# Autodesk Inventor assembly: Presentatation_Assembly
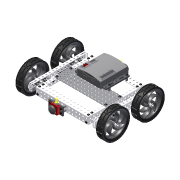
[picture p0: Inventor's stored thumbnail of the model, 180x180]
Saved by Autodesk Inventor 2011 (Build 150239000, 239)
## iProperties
Created: 2007-12
Part Number: Presentatation_Assembly
Document SubType Name: Assembly
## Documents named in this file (15)
- C:\Data Folder\VEX 2011\Inventor Datasets\Unit 16\Wiring_Assembly.iam
- C:\Data Folder\VEX 2011\Inventor Datasets\Unit 16\Components\SCREW-832-0250.ipt
- C:\Data Folder\VEX 2011\Inventor Datasets\Unit 16\Components\NUT-832-KEPS.iam
- C:\Data Folder\VEX 2011\Inventor Datasets\Unit 16\Components\VL-RAIL-21-16 RevA.ipt
- C:\Data Folder\VEX 2011\Inventor Datasets\Unit 16\Components\ANG-HH22-15-SK RevA.ipt
- C:\Data Folder\VEX 2011\Inventor Datasets\Unit 16\Components\VL-PLATE-5-15 RevA.ipt
- C:\Data Folder\VEX 2011\Inventor Datasets\Unit 16\Components\Wheel _Assembly.iam
- C:\Data Folder\VEX 2011\Inventor Datasets\Unit 16\Components\BEAM-0500.ipt
- C:\Data Folder\VEX 2011\Inventor Datasets\Unit 16\Components\MicroController View.iam
- C:\Data Folder\VEX 2011\Inventor Datasets\Unit 16\Components\BUMPER-SWITCH.iam
- C:\Data Folder\VEX 2011\Inventor Datasets\Unit 16\Components\BUMPER-SWITCH_MIR.iam
- C:\Data Folder\VEX 2011\Inventor Datasets\Unit 16\Components\BEAM-0500_MIR.ipt
- C:\Data Folder\VEX 2011\Inventor Datasets\Unit 16\Connector_01.ipt
- C:\Data Folder\VEX 2011\Inventor Datasets\Unit 16\Content Center\en-US\ANSI B18.3(03)\ANSI B18.3 - 8-32 UNC - UNC - 0.5(1).ipt
- C:\Data Folder\VEX 2011\Inventor Datasets\Unit 16\Content Center\en-US\ANSI B18.3(03)\ANSI B18.3 - 8-32 UNC - UNC - 0.375(1).ipt
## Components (70 placed, 14 different names)
1. BEAM-0500:1 — Mate:151, Mate:152
2. SCREW-832-0250:1 — Mate:57, Flush:10
3. SCREW-832-0250:6
4. SCREW-832-0250:14 — Mate:56, Flush:10
5. SCREW-832-0250:18
6. SCREW-832-0250:20
7. SCREW-832-0250:21
8. NUT-832-KEPS:14 [sub-assembly]
9. NUT-832-KEPS:16 [sub-assembly] — Mate:54, Mate:55, Mate:56
10. NUT-832-KEPS:17 [sub-assembly]
11. NUT-832-KEPS:18 [sub-assembly] — Mate:57, Mate:58
12. NUT-832-KEPS:19 [sub-assembly]
13. NUT-832-KEPS:20 [sub-assembly]
14. NUT-832-KEPS:21 [sub-assembly]
15. NUT-832-KEPS:22 [sub-assembly]
16. NUT-832-KEPS:23 [sub-assembly]
17. SCREW-832-0250:25
18. SCREW-832-0250:34
19. SCREW-832-0250:30 — Mate:59, Mate:60, Mate:61
20. ANG-HH22-15-SK RevA:1 — Mate:2, Mate:3, Mate:4, Flush:2, Mate:6, Mate:154, Mate:156
21. NUT-832-KEPS:24 [sub-assembly] — Mate:183, Mate:184
22. SCREW-832-0250:40
23. SCREW-832-0250:42
24. SCREW-832-0250:43 — Mate:169, Mate:170
25. SCREW-832-0250:44 — Mate:163, Mate:164
26. SCREW-832-0250:45 — Mate:165, Mate:166
27. SCREW-832-0250:46 — Mate:167, Mate:168
28. SCREW-832-0250:47 — Mate:171, Mate:172, Mate:173
29. SCREW-832-0250:48 — Mate:179, Mate:180, Mate:183
30. SCREW-832-0250:49 — Mate:175, Mate:176, Mate:181
31. SCREW-832-0250:50 — Mate:177, Mate:178, Mate:185
32. NUT-832-KEPS:31 [sub-assembly] — Mate:181, Mate:182
33. NUT-832-KEPS:32 [sub-assembly] — Mate:185, Mate:186
34. VL-RAIL-21-16 RevA:3 — Mate:2, Mate:3, Mate:4, Flush:3, Mate:8, Mate:9, Mate:54, Mate:55, Mate:58, Mate:59, Mate:60, Mate:62, Flush:12, Mate:148, Mate:149, Mate:150, Mate:177, Mate:179, Mate:184, Mate:186
35. NUT-832-KEPS:28 [sub-assembly] — Mate:61, Mate:62
36. VL-RAIL-21-16 RevA:4 — Flush:2, Mate:6, Mate:102, Mate:159, Mate:160, Mate:161, Mate:162, Mate:171, Mate:174, Mate:175, Mate:182
37. ANG-HH22-15-SK RevA:2 — Flush:3, Mate:8, Mate:9, Mate:113, Angle:2, Mate:114, Mate:160, Mate:164, Mate:166, Mate:168, Mate:170
38. NUT-832-KEPS:27 [sub-assembly] — Mate:173, Mate:174
39. NUT-832-KEPS:30 [sub-assembly]
40. VL-PLATE-5-15 RevA:1 — Mate:102, Mate:158, Mate:172, Mate:176, Mate:178, Mate:180
41. Wheel _Assembly:1 [sub-assembly] — Flush:12, Mate:148, Mate:149, Mate:150
42. Wheel _Assembly:2 [sub-assembly] — Mate:159, Mate:161, Mate:162
43. MicroController View:1 [sub-assembly] — Mate:128, Mate:129, Mate:132, Mate:133, Mate:134, Mate:135, Mate:136, Mate:137, Mate:138, Mate:139, Mate:152, Mate:187, Mate:188
44. BUMPER-SWITCH:1 [sub-assembly] — Mate:115, Mate:116, Mate:117, Mate:140, Mate:142, Mate:144, Mate:146
45. BUMPER-SWITCH_MIR:1 [sub-assembly] — Mate:118, Mate:119, Mate:120, Insert:1, Insert:2, Insert:3, Insert:4
46. BEAM-0500_MIR:1
47. BEAM-0500_MIR:2 — Mate:118
48. BEAM-0500_MIR:3
49. BEAM-0500_MIR:4 — Mate:119, Mate:120
50. Hexagon Socket Button Head Cap Screw - Inch 8 - 32 x 1/2:3 — Mate:136, Mate:137, Mate:157
51. Hexagon Socket Button Head Cap Screw - Inch 8 - 32 x 1/2:1 — Mate:132, Mate:133, Mate:151
52. Hexagon Socket Button Head Cap Screw - Inch 8 - 32 x 1/2:2 — Mate:134, Mate:135, Mate:153
53. Hexagon Socket Button Head Cap Screw - Inch 8 - 32 x 1/2:4 — Mate:138, Mate:139, Mate:155
54. Hexagon Socket Button Head Cap Screw - Inch 8 - 32 x 3/8:1 — Mate:140, Mate:141
55. Hexagon Socket Button Head Cap Screw - Inch 8 - 32 x 3/8:2 — Mate:142, Mate:143
56. Hexagon Socket Button Head Cap Screw - Inch 8 - 32 x 3/8:3 — Mate:146, Mate:147
57. Hexagon Socket Button Head Cap Screw - Inch 8 - 32 x 3/8:4 — Mate:144, Mate:145
58. BEAM-0500:9 — Mate:153, Mate:154
59. BEAM-0500:10 — Mate:155, Mate:156
60. BEAM-0500:11 — Mate:157, Mate:158
61. Hexagon Socket Button Head Cap Screw - Inch 8 - 32 x 1/2:5 — Insert:4
62. Hexagon Socket Button Head Cap Screw - Inch 8 - 32 x 1/2:6 — Insert:3
63. Hexagon Socket Button Head Cap Screw - Inch 8 - 32 x 1/2:7 — Insert:2
64. Hexagon Socket Button Head Cap Screw - Inch 8 - 32 x 3/8:5 — Insert:1
65. Connector_01:1 — Mate:128, Mate:129, Flush:13
66. Connector_01:2 — Flush:13, Mate:187, Mate:188
67. BEAM-0500:5 — Mate:113, Angle:2, Mate:114, Mate:147, Mate:169
68. BEAM-0500:6 — Mate:116, Mate:143, Mate:165
69. BEAM-0500:7 — Mate:145, Mate:167
70. BEAM-0500:8 — Mate:115, Mate:117, Mate:141, Mate:163
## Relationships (93: Mate 83, Flush 5, Insert 4, Angle 1)
- Mate:2: ANG-HH22-15-SK RevA:1 ↔ VL-RAIL-21-16 RevA:3
- Mate:3: ANG-HH22-15-SK RevA:1 ↔ VL-RAIL-21-16 RevA:3
- Mate:4: ANG-HH22-15-SK RevA:1 ↔ VL-RAIL-21-16 RevA:3
- Flush:2: ANG-HH22-15-SK RevA:1 ↔ VL-RAIL-21-16 RevA:4
- Mate:6: ANG-HH22-15-SK RevA:1 ↔ VL-RAIL-21-16 RevA:4
- Flush:3: VL-RAIL-21-16 RevA:3 ↔ ANG-HH22-15-SK RevA:2
- Mate:8: VL-RAIL-21-16 RevA:3 ↔ ANG-HH22-15-SK RevA:2
- Mate:9: VL-RAIL-21-16 RevA:3 ↔ ANG-HH22-15-SK RevA:2
- Mate:54: NUT-832-KEPS:16 ↔ VL-RAIL-21-16 RevA:3
- Mate:55: NUT-832-KEPS:16 ↔ VL-RAIL-21-16 RevA:3
- Mate:56: SCREW-832-0250:14 ↔ NUT-832-KEPS:16
- Mate:57: SCREW-832-0250:1 ↔ NUT-832-KEPS:18
- Mate:58: NUT-832-KEPS:18 ↔ VL-RAIL-21-16 RevA:3
- Flush:10: SCREW-832-0250:1 ↔ SCREW-832-0250:14
- Mate:59: SCREW-832-0250:30 ↔ VL-RAIL-21-16 RevA:3
- Mate:60: SCREW-832-0250:30 ↔ VL-RAIL-21-16 RevA:3
- Mate:61: SCREW-832-0250:30 ↔ NUT-832-KEPS:28
- Mate:62: VL-RAIL-21-16 RevA:3 ↔ NUT-832-KEPS:28
- Mate:102: VL-RAIL-21-16 RevA:4 ↔ VL-PLATE-5-15 RevA:1
- Mate:113: ANG-HH22-15-SK RevA:2 ↔ BEAM-0500:5
- Angle:2: ANG-HH22-15-SK RevA:2 ↔ BEAM-0500:5
- Mate:114: ANG-HH22-15-SK RevA:2 ↔ BEAM-0500:5
- Mate:115: BUMPER-SWITCH:1 ↔ BEAM-0500:8
- Mate:116: BUMPER-SWITCH:1 ↔ BEAM-0500:6
- Mate:117: BUMPER-SWITCH:1 ↔ BEAM-0500:8
- Mate:118: BUMPER-SWITCH_MIR:1 ↔ BEAM-0500_MIR:2
- Mate:119: BUMPER-SWITCH_MIR:1 ↔ BEAM-0500_MIR:4
- Mate:120: BUMPER-SWITCH_MIR:1 ↔ BEAM-0500_MIR:4
- Mate:128: MicroController View:1 ↔ Connector_01:1
- Mate:129: MicroController View:1 ↔ Connector_01:1
- Mate:132: MicroController View:1 ↔ Hexagon Socket Button Head Cap Screw - Inch 8 - 32 x 1/2:1
- Mate:133: MicroController View:1 ↔ Hexagon Socket Button Head Cap Screw - Inch 8 - 32 x 1/2:1
- Mate:134: MicroController View:1 ↔ Hexagon Socket Button Head Cap Screw - Inch 8 - 32 x 1/2:2
- Mate:135: MicroController View:1 ↔ Hexagon Socket Button Head Cap Screw - Inch 8 - 32 x 1/2:2
- Mate:136: MicroController View:1 ↔ Hexagon Socket Button Head Cap Screw - Inch 8 - 32 x 1/2:3
- Mate:137: MicroController View:1 ↔ Hexagon Socket Button Head Cap Screw - Inch 8 - 32 x 1/2:3
- Mate:138: MicroController View:1 ↔ Hexagon Socket Button Head Cap Screw - Inch 8 - 32 x 1/2:4
- Mate:139: MicroController View:1 ↔ Hexagon Socket Button Head Cap Screw - Inch 8 - 32 x 1/2:4
- Mate:140: BUMPER-SWITCH:1 ↔ Hexagon Socket Button Head Cap Screw - Inch 8 - 32 x 3/8:1
- Mate:141: Hexagon Socket Button Head Cap Screw - Inch 8 - 32 x 3/8:1 ↔ BEAM-0500:8
- Mate:142: BUMPER-SWITCH:1 ↔ Hexagon Socket Button Head Cap Screw - Inch 8 - 32 x 3/8:2
- Mate:143: Hexagon Socket Button Head Cap Screw - Inch 8 - 32 x 3/8:2 ↔ BEAM-0500:6
- Mate:144: BUMPER-SWITCH:1 ↔ Hexagon Socket Button Head Cap Screw - Inch 8 - 32 x 3/8:4
- Mate:145: Hexagon Socket Button Head Cap Screw - Inch 8 - 32 x 3/8:4 ↔ BEAM-0500:7
- Mate:146: BUMPER-SWITCH:1 ↔ Hexagon Socket Button Head Cap Screw - Inch 8 - 32 x 3/8:3
- Mate:147: Hexagon Socket Button Head Cap Screw - Inch 8 - 32 x 3/8:3 ↔ BEAM-0500:5
- Flush:12: VL-RAIL-21-16 RevA:3 ↔ Wheel _Assembly:1
- Mate:148: VL-RAIL-21-16 RevA:3 ↔ Wheel _Assembly:1
- Mate:149: VL-RAIL-21-16 RevA:3 ↔ Wheel _Assembly:1
- Mate:150: VL-RAIL-21-16 RevA:3 ↔ Wheel _Assembly:1
- Mate:151: BEAM-0500:1 ↔ Hexagon Socket Button Head Cap Screw - Inch 8 - 32 x 1/2:1
- Mate:152: BEAM-0500:1 ↔ MicroController View:1
- Mate:153: Hexagon Socket Button Head Cap Screw - Inch 8 - 32 x 1/2:2 ↔ BEAM-0500:9
- Mate:154: ANG-HH22-15-SK RevA:1 ↔ BEAM-0500:9
- Mate:155: Hexagon Socket Button Head Cap Screw - Inch 8 - 32 x 1/2:4 ↔ BEAM-0500:10
- Mate:156: ANG-HH22-15-SK RevA:1 ↔ BEAM-0500:10
- Mate:157: Hexagon Socket Button Head Cap Screw - Inch 8 - 32 x 1/2:3 ↔ BEAM-0500:11
- Mate:158: VL-PLATE-5-15 RevA:1 ↔ BEAM-0500:11
- Mate:159: VL-RAIL-21-16 RevA:4 ↔ Wheel _Assembly:2
- Mate:160: VL-RAIL-21-16 RevA:4 ↔ ANG-HH22-15-SK RevA:2
- Mate:161: VL-RAIL-21-16 RevA:4 ↔ Wheel _Assembly:2
- Mate:162: VL-RAIL-21-16 RevA:4 ↔ Wheel _Assembly:2
- Mate:163: SCREW-832-0250:44 ↔ BEAM-0500:8
- Mate:164: SCREW-832-0250:44 ↔ ANG-HH22-15-SK RevA:2
- Mate:165: SCREW-832-0250:45 ↔ BEAM-0500:6
- Mate:166: SCREW-832-0250:45 ↔ ANG-HH22-15-SK RevA:2
- Mate:167: SCREW-832-0250:46 ↔ BEAM-0500:7
- Mate:168: SCREW-832-0250:46 ↔ ANG-HH22-15-SK RevA:2
- Mate:169: SCREW-832-0250:43 ↔ BEAM-0500:5
- Mate:170: SCREW-832-0250:43 ↔ ANG-HH22-15-SK RevA:2
- Mate:171: SCREW-832-0250:47 ↔ VL-RAIL-21-16 RevA:4
- Mate:172: SCREW-832-0250:47 ↔ VL-PLATE-5-15 RevA:1
- Mate:173: SCREW-832-0250:47 ↔ NUT-832-KEPS:27
- Mate:174: VL-RAIL-21-16 RevA:4 ↔ NUT-832-KEPS:27
- Mate:175: SCREW-832-0250:49 ↔ VL-RAIL-21-16 RevA:4
- Mate:176: SCREW-832-0250:49 ↔ VL-PLATE-5-15 RevA:1
- Mate:177: SCREW-832-0250:50 ↔ VL-RAIL-21-16 RevA:3
- Mate:178: SCREW-832-0250:50 ↔ VL-PLATE-5-15 RevA:1
- Mate:179: SCREW-832-0250:48 ↔ VL-RAIL-21-16 RevA:3
- Mate:180: SCREW-832-0250:48 ↔ VL-PLATE-5-15 RevA:1
- Mate:181: SCREW-832-0250:49 ↔ NUT-832-KEPS:31
- Mate:182: NUT-832-KEPS:31 ↔ VL-RAIL-21-16 RevA:4
- Mate:183: NUT-832-KEPS:24 ↔ SCREW-832-0250:48
- Mate:184: NUT-832-KEPS:24 ↔ VL-RAIL-21-16 RevA:3
- Mate:185: SCREW-832-0250:50 ↔ NUT-832-KEPS:32
- Mate:186: NUT-832-KEPS:32 ↔ VL-RAIL-21-16 RevA:3
- Insert:1: BUMPER-SWITCH_MIR:1 ↔ Hexagon Socket Button Head Cap Screw - Inch 8 - 32 x 3/8:5
- Insert:2: BUMPER-SWITCH_MIR:1 ↔ Hexagon Socket Button Head Cap Screw - Inch 8 - 32 x 1/2:7
- Insert:3: BUMPER-SWITCH_MIR:1 ↔ Hexagon Socket Button Head Cap Screw - Inch 8 - 32 x 1/2:6
- Insert:4: BUMPER-SWITCH_MIR:1 ↔ Hexagon Socket Button Head Cap Screw - Inch 8 - 32 x 1/2:5
- Flush:13: Connector_01:1 ↔ Connector_01:2
- Mate:187: MicroController View:1 ↔ Connector_01:2
- Mate:188: MicroController View:1 ↔ Connector_01:2
